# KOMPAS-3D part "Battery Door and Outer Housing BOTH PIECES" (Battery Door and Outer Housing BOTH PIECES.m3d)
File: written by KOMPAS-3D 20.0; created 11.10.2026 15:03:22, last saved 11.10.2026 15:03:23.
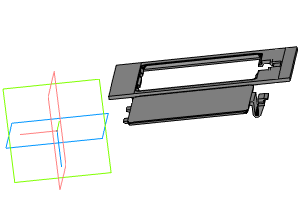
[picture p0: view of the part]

Document properties: Полное имя файла: D:\myProjects\Progect_esp32\box_compas\Battery Door and Outer Housing BOTH PIECES.m3d

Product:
- Part/product: Battery Door and Outer Housing BOTH PIECES
    Масса: 0.0897784
  - Body: Тело 2
      Масса: 0.0407699
  - Body: Тело 1
      Масса: 0.0490085

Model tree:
1. Операция без истории:1
2. Операция без истории:2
